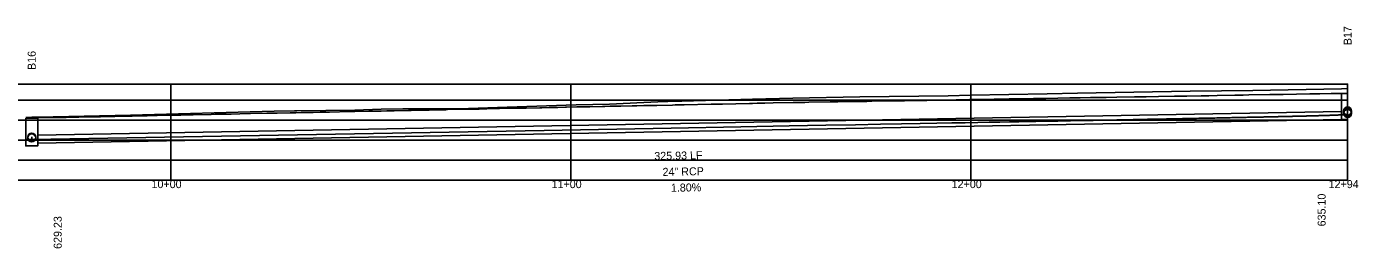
# Model space of a CAD drawing. Extents: x 2253035 to 2279930, y 13774972 to 13793443.
# Drawn here: x 2259349.4 to 2259682.3, y 13793387.2 to 13793442.5 of the extents above; entities that cross this region are included whole.
import ezdxf

# ---------------------------------------------------------------- set-up
doc = ezdxf.new("R2010")
doc.units = 0
for name, color, linetype in [('Default', 7, 'Continuous'), ('E_Utility_ATT_HH', 7, 'Continuous'), ('E_Utility_ATT_PR_PVC', 7, 'Continuous'), ('E_Utility_Electric_Overhead Electric Power Line_OE_Elevation', 7, 'Continuous'), ('E_Utility_Electric_Overhead Electric Power Line_OE_point', 7, 'Continuous'), ('E_Utillity_Water_Water Line_12in', 7, 'Continuous'), ('E_Utillity_Water_Water Line_1in', 7, 'Continuous'), ('E_Utillity_Water_Water Line_4in', 7, 'Continuous'), ('E_Utillity_Water_Water Line_8in', 7, 'Continuous')]:
    doc.layers.add(name, color=color, linetype=linetype)

msp = doc.modelspace()

# ---------------------------------------------------------------- linework, layer by layer
at = {"layer": 'Default'}
for p, q in [((2259385.4, 13793404.21), (2259385.4, 13793428.21)), ((2259485.4, 13793404.21), (2259485.4, 13793428.21)), ((2259585.4, 13793404.21), (2259585.4, 13793428.21))]:
    msp.add_line(p, q, dxfattribs=at)
at = {"layer": 'E_Utility_ATT_PR_PVC'}
msp.add_line((2259350.65, 13793414.99), (2259350.65, 13793414.33), dxfattribs=at)
for points in [[(2259350.65, 13793414.33), (2259478.74, 13793416.64), (2259510.45, 13793417.21), (2259527.94, 13793417.52), (2259540, 13793417.74), (2259549.17, 13793417.91), (2259556.58, 13793418.04), (2259562.78, 13793418.15), (2259568.1, 13793418.25), (2259572.76, 13793418.34), (2259576.91, 13793418.41), (2259580.64, 13793418.48), (2259584.02, 13793418.54), (2259587.12, 13793418.6), (2259589.98, 13793418.65), (2259592.63, 13793418.7), (2259595.09, 13793418.75), (2259597.4, 13793418.79), (2259599.57, 13793418.83), (2259601.61, 13793418.87), (2259603.53, 13793418.9), (2259605.36, 13793418.93), (2259607.1, 13793418.97), (2259608.75, 13793419), (2259610.32, 13793419.03), (2259611.83, 13793419.06), (2259613.27, 13793419.08), (2259614.65, 13793419.11), (2259615.98, 13793419.13), (2259617.25, 13793419.16), (2259618.48, 13793419.18), (2259619.67, 13793419.2), (2259620.81, 13793419.22), (2259621.91, 13793419.24), (2259622.98, 13793419.26), (2259624.01, 13793419.28), (2259625.01, 13793419.3), (2259625.97, 13793419.32), (2259626.91, 13793419.34), (2259627.82, 13793419.36), (2259628.71, 13793419.37), (2259629.57, 13793419.39), (2259630.4, 13793419.41), (2259631.22, 13793419.42), (2259632.01, 13793419.44), (2259632.78, 13793419.45), (2259633.53, 13793419.47), (2259634.27, 13793419.48), (2259634.98, 13793419.5), (2259635.68, 13793419.51), (2259636.36, 13793419.52), (2259637.02, 13793419.53), (2259637.67, 13793419.55), (2259638.31, 13793419.56), (2259638.93, 13793419.57), (2259639.54, 13793419.58), (2259640.13, 13793419.6), (2259640.72, 13793419.61), (2259641.29, 13793419.62), (2259641.84, 13793419.63), (2259642.39, 13793419.64), (2259642.93, 13793419.65), (2259643.45, 13793419.66), (2259643.97, 13793419.67), (2259644.47, 13793419.68), (2259644.96, 13793419.69), (2259645.45, 13793419.7), (2259645.93, 13793419.71), (2259646.39, 13793419.72), (2259646.85, 13793419.73), (2259647.31, 13793419.74), (2259647.75, 13793419.75), (2259648.18, 13793419.76), (2259648.61, 13793419.77), (2259649.03, 13793419.77), (2259649.44, 13793419.78), (2259649.85, 13793419.79), (2259650.25, 13793419.8), (2259650.64, 13793419.81), (2259651.03, 13793419.81), (2259651.41, 13793419.82), (2259651.78, 13793419.83), (2259652.15, 13793419.84), (2259652.51, 13793419.85), (2259652.86, 13793419.85), (2259653.22, 13793419.86), (2259653.56, 13793419.87), (2259653.9, 13793419.87), (2259654.23, 13793419.88), (2259654.56, 13793419.89), (2259654.89, 13793419.9), (2259655.21, 13793419.9), (2259655.52, 13793419.91), (2259655.83, 13793419.92), (2259656.14, 13793419.92), (2259656.44, 13793419.93), (2259656.74, 13793419.93), (2259657.03, 13793419.94), (2259657.32, 13793419.95), (2259657.6, 13793419.95), (2259657.88, 13793419.96), (2259658.16, 13793419.97), (2259658.43, 13793419.97), (2259658.7, 13793419.98), (2259658.96, 13793419.98), (2259659.23, 13793419.99), (2259659.48, 13793419.99), (2259659.74, 13793420), (2259659.99, 13793420.01), (2259660.24, 13793420.01), (2259660.48, 13793420.02), (2259660.72, 13793420.02), (2259660.96, 13793420.03), (2259661.2, 13793420.03), (2259661.43, 13793420.04), (2259661.66, 13793420.04), (2259661.88, 13793420.05), (2259662.11, 13793420.05), (2259662.33, 13793420.06), (2259662.54, 13793420.06), (2259662.76, 13793420.07), (2259662.97, 13793420.07), (2259663.18, 13793420.08), (2259663.39, 13793420.08), (2259663.59, 13793420.09), (2259663.79, 13793420.09), (2259663.99, 13793420.1), (2259664.19, 13793420.1), (2259664.38, 13793420.1), (2259664.57, 13793420.11), (2259664.76, 13793420.11), (2259664.95, 13793420.12), (2259665.14, 13793420.12), (2259665.32, 13793420.13), (2259665.5, 13793420.13), (2259665.68, 13793420.13), (2259665.85, 13793420.14), (2259666.03, 13793420.14), (2259666.2, 13793420.15), (2259666.37, 13793420.15), (2259666.54, 13793420.16), (2259666.7, 13793420.16), (2259666.87, 13793420.16), (2259667.03, 13793420.17), (2259667.19, 13793420.17), (2259667.35, 13793420.17), (2259667.51, 13793420.18), (2259667.66, 13793420.18), (2259667.81, 13793420.19), (2259667.97, 13793420.19), (2259668.12, 13793420.19), (2259668.26, 13793420.2), (2259668.41, 13793420.2), (2259668.55, 13793420.2), (2259668.7, 13793420.21), (2259668.84, 13793420.21), (2259668.98, 13793420.22), (2259669.12, 13793420.22), (2259669.25, 13793420.22), (2259669.39, 13793420.23), (2259669.52, 13793420.23), (2259669.65, 13793420.23), (2259669.78, 13793420.24), (2259669.91, 13793420.24), (2259670.04, 13793420.24), (2259670.17, 13793420.25), (2259670.29, 13793420.25), (2259670.41, 13793420.25), (2259670.54, 13793420.26), (2259670.66, 13793420.26), (2259670.78, 13793420.26), (2259670.89, 13793420.26), (2259671.01, 13793420.27), (2259671.13, 13793420.27), (2259671.24, 13793420.27), (2259671.35, 13793420.28), (2259671.47, 13793420.28), (2259671.58, 13793420.28), (2259671.69, 13793420.29), (2259671.79, 13793420.29), (2259671.9, 13793420.29), (2259672.01, 13793420.29), (2259672.11, 13793420.3), (2259672.21, 13793420.3), (2259672.32, 13793420.3), (2259672.42, 13793420.31), (2259672.52, 13793420.31), (2259672.62, 13793420.31), (2259672.71, 13793420.31), (2259672.81, 13793420.32), (2259672.91, 13793420.32), (2259673, 13793420.32), (2259673.09, 13793420.33), (2259673.19, 13793420.33), (2259673.28, 13793420.33), (2259673.37, 13793420.33), (2259673.46, 13793420.34), (2259673.55, 13793420.34), (2259673.63, 13793420.34), (2259673.72, 13793420.34), (2259673.81, 13793420.35), (2259673.89, 13793420.35), (2259673.97, 13793420.35), (2259674.06, 13793420.35), (2259674.14, 13793420.36), (2259674.22, 13793420.36), (2259674.3, 13793420.36), (2259674.38, 13793420.36), (2259674.46, 13793420.37), (2259674.53, 13793420.37), (2259674.61, 13793420.37), (2259674.69, 13793420.37), (2259674.76, 13793420.38), (2259674.83, 13793420.38), (2259674.91, 13793420.38), (2259674.98, 13793420.38), (2259675.05, 13793420.38), (2259675.12, 13793420.39), (2259675.19, 13793420.39), (2259675.26, 13793420.39), (2259675.33, 13793420.39), (2259675.4, 13793420.4), (2259675.46, 13793420.4), (2259675.53, 13793420.4), (2259675.6, 13793420.4), (2259675.66, 13793420.4), (2259675.72, 13793420.41), (2259675.79, 13793420.41), (2259675.85, 13793420.41), (2259675.91, 13793420.41), (2259675.97, 13793420.41), (2259676.03, 13793420.42), (2259676.09, 13793420.42), (2259676.15, 13793420.42), (2259676.21, 13793420.42), (2259676.27, 13793420.43), (2259676.32, 13793420.43), (2259676.38, 13793420.43), (2259676.44, 13793420.43), (2259676.49, 13793420.43), (2259676.54, 13793420.44), (2259676.6, 13793420.44), (2259676.65, 13793420.44), (2259676.7, 13793420.44), (2259676.75, 13793420.45), (2259676.81, 13793420.45), (2259676.86, 13793420.45), (2259676.91, 13793420.45), (2259676.96, 13793420.46), (2259677, 13793420.46), (2259677.05, 13793420.46), (2259677.1, 13793420.47), (2259677.15, 13793420.47), (2259677.19, 13793420.47), (2259677.24, 13793420.47), (2259677.28, 13793420.48), (2259677.33, 13793420.48), (2259677.37, 13793420.48), (2259677.41, 13793420.48), (2259677.46, 13793420.49), (2259677.5, 13793420.49), (2259677.54, 13793420.49), (2259677.58, 13793420.49), (2259677.62, 13793420.5), (2259677.66, 13793420.5), (2259677.7, 13793420.5), (2259677.74, 13793420.5), (2259677.78, 13793420.51), (2259677.82, 13793420.51), (2259677.86, 13793420.51), (2259677.89, 13793420.51), (2259677.93, 13793420.52), (2259677.97, 13793420.52), (2259678, 13793420.52), (2259678.04, 13793420.52), (2259678.07, 13793420.52), (2259678.11, 13793420.53), (2259678.14, 13793420.53), (2259678.17, 13793420.53), (2259678.21, 13793420.53), (2259678.24, 13793420.54), (2259678.27, 13793420.54), (2259678.3, 13793420.54), (2259678.33, 13793420.54), (2259678.36, 13793420.54), (2259678.39, 13793420.55), (2259678.42, 13793420.55), (2259678.45, 13793420.55), (2259678.48, 13793420.55), (2259678.51, 13793420.55), (2259678.53, 13793420.56), (2259678.56, 13793420.56), (2259678.59, 13793420.56), (2259678.61, 13793420.56), (2259678.64, 13793420.56), (2259678.67, 13793420.57), (2259678.69, 13793420.57), (2259678.72, 13793420.57), (2259678.74, 13793420.57), (2259678.76, 13793420.57), (2259678.79, 13793420.58), (2259678.81, 13793420.58), (2259678.83, 13793420.58), (2259678.86, 13793420.58), (2259678.88, 13793420.58), (2259678.9, 13793420.58), (2259678.92, 13793420.59), (2259678.94, 13793420.59), (2259678.96, 13793420.59), (2259678.98, 13793420.59), (2259679, 13793420.59), (2259679.02, 13793420.59), (2259679.04, 13793420.6), (2259679.06, 13793420.6), (2259679.08, 13793420.6), (2259679.09, 13793420.6), (2259679.11, 13793420.6), (2259679.13, 13793420.6), (2259679.15, 13793420.61), (2259679.16, 13793420.61), (2259679.18, 13793420.61), (2259679.19, 13793420.61), (2259679.21, 13793420.61), (2259679.22, 13793420.61), (2259679.24, 13793420.62), (2259679.25, 13793420.62), (2259679.27, 13793420.62), (2259679.28, 13793420.62), (2259679.29, 13793420.62), (2259679.31, 13793420.62), (2259679.32, 13793420.62), (2259679.33, 13793420.63), (2259679.34, 13793420.63), (2259679.36, 13793420.63), (2259679.37, 13793420.63), (2259679.38, 13793420.63), (2259679.39, 13793420.63), (2259679.4, 13793420.63), (2259679.41, 13793420.64), (2259679.42, 13793420.64), (2259679.43, 13793420.64), (2259679.44, 13793420.64), (2259679.45, 13793420.64), (2259679.46, 13793420.64), (2259679.46, 13793420.64), (2259679.47, 13793420.64), (2259679.48, 13793420.65), (2259679.49, 13793420.65), (2259679.49, 13793420.65), (2259679.5, 13793420.65), (2259679.51, 13793420.65), (2259679.51, 13793420.65), (2259679.52, 13793420.65), (2259679.53, 13793420.65), (2259679.53, 13793420.66), (2259679.54, 13793420.66), (2259679.54, 13793420.66), (2259679.55, 13793420.66), (2259679.55, 13793420.66), (2259679.55, 13793420.66), (2259679.56, 13793420.66), (2259679.56, 13793420.66), (2259679.56, 13793420.67), (2259679.57, 13793420.67), (2259679.57, 13793420.67), (2259679.57, 13793420.67), (2259679.57, 13793420.67), (2259679.58, 13793420.67), (2259679.58, 13793420.67), (2259679.58, 13793420.67), (2259679.58, 13793420.67), (2259679.58, 13793420.67), (2259679.58, 13793420.68), (2259679.58, 13793420.68), (2259679.58, 13793420.68), (2259679.58, 13793421.19)], [(2259349.38, 13793414.33), (2259349.42, 13793414.33), (2259349.47, 13793414.34), (2259349.51, 13793414.34), (2259349.56, 13793414.34), (2259349.6, 13793414.34), (2259349.64, 13793414.34), (2259349.68, 13793414.35), (2259349.72, 13793414.35), (2259349.76, 13793414.35), (2259349.79, 13793414.35), (2259349.83, 13793414.35), (2259349.86, 13793414.35), (2259349.9, 13793414.36), (2259349.93, 13793414.36), (2259349.96, 13793414.36), (2259350, 13793414.36), (2259350.03, 13793414.36), (2259350.06, 13793414.37), (2259350.09, 13793414.37), (2259350.12, 13793414.37), (2259350.14, 13793414.37), (2259350.17, 13793414.37), (2259350.2, 13793414.37), (2259350.22, 13793414.38), (2259350.25, 13793414.38), (2259350.27, 13793414.38), (2259350.29, 13793414.38), (2259350.31, 13793414.38), (2259350.34, 13793414.38), (2259350.36, 13793414.38), (2259350.38, 13793414.39), (2259350.4, 13793414.39), (2259350.41, 13793414.39), (2259350.43, 13793414.39), (2259350.45, 13793414.39), (2259350.46, 13793414.39), (2259350.48, 13793414.39), (2259350.49, 13793414.4), (2259350.51, 13793414.4), (2259350.52, 13793414.4), (2259350.53, 13793414.4), (2259350.55, 13793414.4), (2259350.56, 13793414.4), (2259350.57, 13793414.4), (2259350.58, 13793414.41), (2259350.59, 13793414.41), (2259350.6, 13793414.41), (2259350.6, 13793414.41), (2259350.61, 13793414.41), (2259350.62, 13793414.41), (2259350.62, 13793414.41), (2259350.63, 13793414.41), (2259350.63, 13793414.41), (2259350.64, 13793414.42), (2259350.64, 13793414.42), (2259350.64, 13793414.42), (2259350.64, 13793414.42), (2259350.65, 13793414.42), (2259350.65, 13793414.42), (2259350.65, 13793414.42), (2259350.65, 13793414.99)]]:
    msp.add_lwpolyline(points, dxfattribs=at)
at = {"layer": 'E_Utility_Electric_Overhead Electric Power Line_OE_Elevation'}
for p, q in [((2258385.4, 13793424.21), (2259679.58, 13793424.21)), ((2258385.4, 13793419.21), (2259679.58, 13793419.21)), ((2258385.4, 13793414.21), (2259679.58, 13793414.21)), ((2258385.4, 13793409.21), (2259679.58, 13793409.21))]:
    msp.add_line(p, q, dxfattribs=at)
at = {"layer": 'E_Utility_Electric_Overhead Electric Power Line_OE_point'}
msp.add_lwpolyline([(2258385.4, 13793404.21), (2258385.4, 13793428.21), (2259679.58, 13793428.21), (2259679.58, 13793404.21)], close=True, dxfattribs=at)
at = {"layer": 'E_Utillity_Water_Water Line_12in'}
for points in [[(2259678.08, 13793425.88), (2259679.58, 13793425.88), (2259679.58, 13793419.31), (2259678.08, 13793419.31)], [(2259349.15, 13793419.7), (2259352.15, 13793419.7), (2259352.15, 13793412.74), (2259349.15, 13793412.74)]]:
    msp.add_lwpolyline(points, close=True, dxfattribs=at)
at = {"layer": 'E_Utillity_Water_Water Line_1in'}
msp.add_lwpolyline([(2259349.15, 13793419.87), (2259350.65, 13793419.91), (2259350.65, 13793419.91), (2259352.15, 13793419.94), (2259352.15, 13793419.94), (2259375.36, 13793420.42), (2259411.27, 13793421.46), (2259416.3, 13793421.54), (2259416.88, 13793421.51), (2259431.42, 13793421.71), (2259437.97, 13793421.96), (2259443.43, 13793422.03), (2259457.43, 13793422.05), (2259469.46, 13793422.39), (2259486.73, 13793423.01), (2259495.1, 13793423.21), (2259503.68, 13793423.6), (2259507.16, 13793423.75), (2259509.68, 13793423.85), (2259513.17, 13793423.96), (2259530.79, 13793424.4), (2259540.94, 13793424.66), (2259557.62, 13793424.99), (2259579.76, 13793425.26), (2259585.35, 13793425.4), (2259604.5, 13793425.74), (2259612.06, 13793425.9), (2259640.2, 13793426.39), (2259655.85, 13793426.62), (2259678.08, 13793427.03), (2259678.08, 13793427.03), (2259679.58, 13793427.06)], dxfattribs=at)
at = {"layer": 'E_Utillity_Water_Water Line_4in'}
for p, q in [((2259352.15, 13793415.45), (2259678.08, 13793421.31)), ((2259352.15, 13793413.45), (2259678.08, 13793419.31))]:
    msp.add_line(p, q, dxfattribs=at)
for centre in [(2259679.58, 13793421.47), (2259679.58, 13793421.19), (2259679.58, 13793420.86), (2259350.65, 13793414.94), (2259350.65, 13793414.75)]:
    msp.add_circle(centre, 1, dxfattribs=at)
at = {"layer": 'E_Utillity_Water_Water Line_8in'}
msp.add_lwpolyline([(2259349.15, 13793419.67), (2259349.48, 13793419.68), (2259350.65, 13793419.7), (2259350.65, 13793419.7), (2259352.15, 13793419.73), (2259352.15, 13793419.73), (2259352.38, 13793419.74), (2259356.04, 13793419.81), (2259357.62, 13793419.85), (2259357.83, 13793419.85), (2259358.95, 13793419.87), (2259359.24, 13793419.88), (2259359.71, 13793419.89), (2259362.43, 13793419.94), (2259365.9, 13793420.01), (2259367.62, 13793420.05), (2259367.81, 13793420.05), (2259369.38, 13793420.08), (2259369.92, 13793420.09), (2259371.42, 13793420.12), (2259375.77, 13793420.21), (2259379.16, 13793420.28), (2259379.52, 13793420.29), (2259381.98, 13793420.34), (2259385.63, 13793420.41), (2259386.51, 13793420.43), (2259386.61, 13793420.43), (2259386.69, 13793420.43), (2259387.9, 13793420.46), (2259389.66, 13793420.49), (2259391.03, 13793420.52), (2259395.5, 13793420.61), (2259396.52, 13793420.64), (2259396.61, 13793420.64), (2259396.69, 13793420.64), (2259397.76, 13793420.66), (2259399.36, 13793420.69), (2259399.8, 13793420.7), (2259400.54, 13793420.71), (2259402.66, 13793420.76), (2259405.36, 13793420.81), (2259409.46, 13793420.9), (2259409.93, 13793420.91), (2259412.04, 13793420.95), (2259415.23, 13793421.01), (2259416.55, 13793421.04), (2259416.61, 13793421.04), (2259416.66, 13793421.04), (2259418.04, 13793421.07), (2259419.56, 13793421.1), (2259420.07, 13793421.11), (2259420.98, 13793421.13), (2259422.78, 13793421.17), (2259425.09, 13793421.21), (2259430.21, 13793421.32), (2259431.38, 13793421.34), (2259434.96, 13793421.41), (2259436.6, 13793421.45), (2259436.61, 13793421.45), (2259436.63, 13793421.45), (2259437.91, 13793421.47), (2259438, 13793421.47), (2259439.39, 13793421.5), (2259440.35, 13793421.52), (2259441.22, 13793421.54), (2259444.82, 13793421.61), (2259445.35, 13793421.62), (2259445.35, 13793421.62), (2259445.47, 13793421.63), (2259445.48, 13793421.63), (2259445.51, 13793421.63), (2259445.51, 13793421.63), (2259445.54, 13793421.63), (2259446.7, 13793421.65), (2259448.08, 13793421.68), (2259450.04, 13793421.72), (2259450.49, 13793421.73), (2259450.84, 13793421.74), (2259451.09, 13793421.74), (2259451.47, 13793421.75), (2259451.5, 13793421.75), (2259451.52, 13793421.75), (2259451.52, 13793421.75), (2259454.19, 13793421.8), (2259454.26, 13793421.81), (2259454.3, 13793421.81), (2259454.31, 13793421.81), (2259454.31, 13793421.81), (2259454.62, 13793421.81), (2259459.28, 13793421.91), (2259460.07, 13793421.92), (2259460.66, 13793421.94), (2259460.89, 13793421.94), (2259462.14, 13793421.97), (2259462.48, 13793421.97), (2259463.12, 13793421.99), (2259464.43, 13793422.01), (2259470.85, 13793422.14), (2259471.12, 13793422.15), (2259473.13, 13793422.19), (2259473.48, 13793422.2), (2259474.24, 13793422.21), (2259477.67, 13793422.28), (2259478.05, 13793422.29), (2259478.19, 13793422.29), (2259480.03, 13793422.33), (2259480.81, 13793422.35), (2259480.98, 13793422.35), (2259481.05, 13793422.35), (2259481.44, 13793422.36), (2259482.14, 13793422.37), (2259484.06, 13793422.41), (2259484.28, 13793422.42), (2259484.28, 13793422.42), (2259484.29, 13793422.42), (2259484.31, 13793422.42), (2259484.31, 13793422.42), (2259484.31, 13793422.42), (2259484.31, 13793422.42), (2259484.32, 13793422.42), (2259486.95, 13793422.47), (2259487.05, 13793422.47), (2259487.95, 13793422.49), (2259488.67, 13793422.51), (2259488.85, 13793422.51), (2259489.03, 13793422.51), (2259489.13, 13793422.52), (2259489.16, 13793422.52), (2259489.2, 13793422.52), (2259489.22, 13793422.52), (2259489.89, 13793422.53), (2259490.19, 13793422.54), (2259493.33, 13793422.6), (2259493.5, 13793422.6), (2259493.87, 13793422.61), (2259495.25, 13793422.64), (2259497.9, 13793422.69), (2259500.73, 13793422.75), (2259500.96, 13793422.76), (2259501.1, 13793422.76), (2259501.39, 13793422.77), (2259501.43, 13793422.77), (2259501.9, 13793422.78), (2259503.68, 13793422.81), (2259506.93, 13793422.88), (2259510.79, 13793422.96), (2259511.53, 13793422.97), (2259511.63, 13793422.97), (2259513.5, 13793423.01), (2259513.57, 13793423.01), (2259513.75, 13793423.02), (2259520.49, 13793423.16), (2259521.82, 13793423.18), (2259522.22, 13793423.19), (2259523.31, 13793423.21), (2259526.69, 13793423.28), (2259530.09, 13793423.35), (2259530.83, 13793423.37), (2259532.01, 13793423.39), (2259533.13, 13793423.41), (2259533.9, 13793423.43), (2259535.96, 13793423.47), (2259540.95, 13793423.57), (2259542.21, 13793423.6), (2259543.02, 13793423.61), (2259543.86, 13793423.63), (2259544.88, 13793423.64), (2259550.23, 13793423.73), (2259550.82, 13793423.74), (2259552.14, 13793423.76), (2259555.06, 13793423.81), (2259556.89, 13793423.84), (2259557.95, 13793423.86), (2259559.37, 13793423.88), (2259560.63, 13793423.9), (2259565.99, 13793423.99), (2259566.5, 13793424), (2259567.11, 13793424.01), (2259567.92, 13793424.03), (2259568.81, 13793424.04), (2259571.21, 13793424.08), (2259574.39, 13793424.13), (2259574.83, 13793424.14), (2259575.67, 13793424.15), (2259576.47, 13793424.17), (2259577.33, 13793424.18), (2259577.92, 13793424.19), (2259579.15, 13793424.21), (2259581.75, 13793424.26), (2259583.34, 13793424.28), (2259583.7, 13793424.29), (2259584.68, 13793424.3), (2259585.02, 13793424.31), (2259585.51, 13793424.32), (2259587.43, 13793424.35), (2259591.19, 13793424.41), (2259593.02, 13793424.44), (2259593.57, 13793424.45), (2259594.97, 13793424.48), (2259599.03, 13793424.54), (2259601.09, 13793424.58), (2259602.12, 13793424.59), (2259603.24, 13793424.61), (2259603.64, 13793424.62), (2259604.15, 13793424.63), (2259610.16, 13793424.73), (2259610.67, 13793424.74), (2259611.41, 13793424.75), (2259612.71, 13793424.77), (2259615.28, 13793424.81), (2259618.08, 13793424.86), (2259619.06, 13793424.88), (2259619.22, 13793424.88), (2259621.89, 13793424.92), (2259626.27, 13793425), (2259626.48, 13793425), (2259627.32, 13793425.01), (2259627.72, 13793425.02), (2259627.77, 13793425.02), (2259627.77, 13793425.02), (2259629.25, 13793425.04), (2259632.34, 13793425.1), (2259636.31, 13793425.16), (2259637.37, 13793425.18), (2259637.79, 13793425.19), (2259639.37, 13793425.21), (2259643, 13793425.27), (2259644.59, 13793425.3), (2259644.86, 13793425.3), (2259646.99, 13793425.34), (2259651.41, 13793425.41), (2259651.86, 13793425.42), (2259651.97, 13793425.42), (2259653.41, 13793425.45), (2259653.47, 13793425.45), (2259654.87, 13793425.47), (2259660.13, 13793425.56), (2259661.96, 13793425.59), (2259663.39, 13793425.61), (2259663.41, 13793425.61), (2259663.45, 13793425.61), (2259670.09, 13793425.72), (2259670.51, 13793425.73), (2259671.13, 13793425.74), (2259672.61, 13793425.76), (2259675.5, 13793425.81), (2259678.08, 13793425.86), (2259678.08, 13793425.86), (2259678.2, 13793425.86), (2259679.06, 13793425.87), (2259679.21, 13793425.87), (2259679.58, 13793425.88)], dxfattribs=at)

# ---------------------------------------------------------------- texts
at = {"layer": 'Default'}
for s, p in [('10+00', (2259380.6, 13793402.21)), ('11+00', (2259480.6, 13793402.21)), ('12+00', (2259580.6, 13793402.21)), ('12+94', (2259674.83, 13793402.21))]:
    msp.add_text(s, height=2, dxfattribs=at).set_placement(p)
at = {"layer": 'E_Utility_ATT_HH'}
for s, rotation, p in [('B17', 90, (2259680.58, 13793437.91)), ('B16', 90, (2259351.65, 13793431.72)), ('325.93 LF', 1.0312, (2259506.29, 13793409.22)), ('24" RCP', 1.0312, (2259508.36, 13793405.26)), ('1.80%', 1.0312, (2259510.44, 13793401.29)), ('635.10', 90, (2259674.08, 13793392.65)), ('629.23', 90, (2259358.15, 13793387.03))]:
    msp.add_text(s, height=2, rotation=rotation, dxfattribs=at).set_placement(p)

doc.saveas('drawing.dxf')
